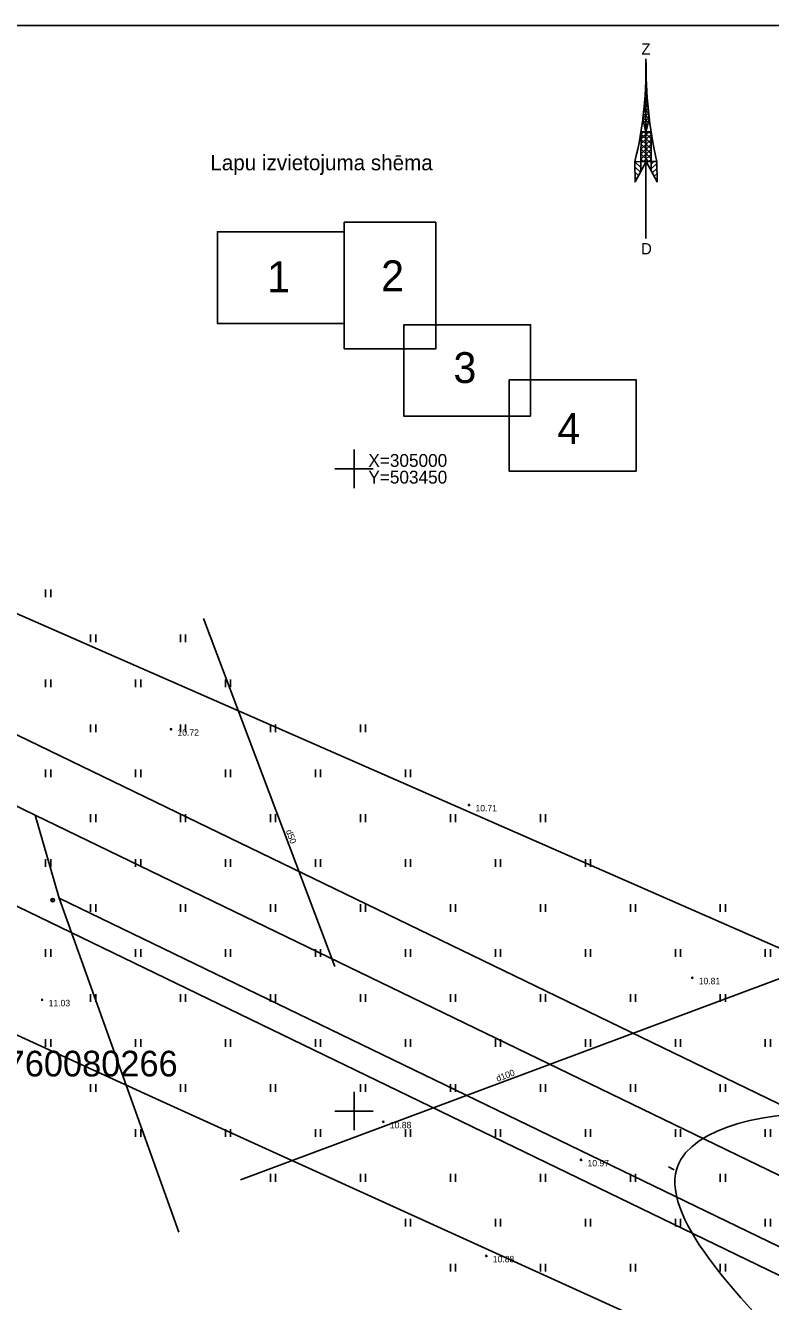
# Model space of a CAD drawing. Extents: x 503353 to 504004, y 304662 to 305049.
# Drawn here: x 503424.4 to 503482.4, y 304935.2 to 305034.5 of the extents above; entities that cross this region are included whole.
import ezdxf

# ---------------------------------------------------------------- set-up
doc = ezdxf.new("R2010")
doc.units = 0
for name, color, linetype in [('20', 7, 'Continuous'), ('24', 7, 'Continuous'), ('25', 7, 'Continuous'), ('59', 7, 'Continuous'), ('APGR_ELEM_####_####_#', 7, 'Continuous'), ('BUVE_ELEM_####_####_#', 7, 'Continuous'), ('DREN_VADP_####_####_#', 7, 'Continuous'), ('DREN_VADP_####_TKST_#', 7, 'Continuous'), ('DREN_VADP_KLKT_####_#', 7, 'Continuous'), ('DREN_VADP_KLKT_TKST_#', 7, 'Continuous'), ('GEOD_ELEM_####_####_#', 7, 'Continuous'), ('GEOD_KORD_####_TKST_#', 7, 'Continuous'), ('RAMI_PLAN_####_TKST_#', 7, 'Continuous'), ('RAMI_UZMR_####_####_#', 7, 'Continuous'), ('RELJ_AATZ_####_TKST_#', 7, 'Continuous'), ('RELJ_ELEM_####_####_#', 7, 'Continuous'), ('RELJ_HORZ_PAMT_####_#', 7, 'Continuous'), ('TERT_ELEM_####_####_#', 7, 'Continuous')]:
    doc.layers.add(name, color=color, linetype=linetype)

msp = doc.modelspace()

# ---------------------------------------------------------------- linework, layer by layer
at = {"layer": '20'}
msp.add_line((503425.185, 304973.036), (503427.051, 304966.576), dxfattribs=at)
at = {"layer": '24'}
for q in [(503436.371, 304940.581), (503597.271, 304884.111)]:
    msp.add_line((503427.051, 304966.576), q, dxfattribs=at)
at = {"layer": '25'}
for p in [(503405.924, 304982.367), (503595.592, 304890.48)]:
    msp.add_line(p, (503425.185, 304973.036), dxfattribs=at)
at = {"layer": 'APGR_ELEM_####_####_#'}
for p, q in [((503412.342, 304984.814), (503586.697, 304900.345)), ((503415.949, 304969.732), (503588.684, 304886.049))]:
    msp.add_line(p, q, dxfattribs=at)
at = {"layer": 'BUVE_ELEM_####_####_#'}
for radius in [0.141, 0.0126]:
    msp.add_circle((503426.558, 304966.417), radius, dxfattribs=at)
at = {"layer": 'DREN_VADP_####_####_#'}
msp.add_line((503438.283, 304988.335), (503448.499, 304961.265), dxfattribs=at)
at = {"layer": 'DREN_VADP_KLKT_####_#'}
msp.add_lwpolyline([(503441.156, 304944.635), (503491.393, 304963.409)], dxfattribs=at)
at = {"layer": 'GEOD_ELEM_####_####_#'}
for p, q in [((503450, 305001.5), (503450, 305000)), ((503448.5, 305000), (503450, 305000)), ((503450, 305000), (503450, 304998.5)), ((503450, 305000), (503451.5, 305000)), ((503450, 304951.5), (503450, 304950)), ((503448.5, 304950), (503450, 304950)), ((503450, 304950), (503450, 304948.5)), ((503450, 304950), (503451.5, 304950))]:
    msp.add_line(p, q, dxfattribs=at)
at = {"layer": 'RAMI_PLAN_####_TKST_#'}
for p, q in [((503472.715, 305031.907), (503472.715, 305017.937)), ((503472.673, 305029.405), (503472.775, 305029.504)), ((503472.675, 305029.469), (503472.783, 305029.366)), ((503472.693, 305029.814), (503472.756, 305029.873)), ((503472.695, 305029.836), (503472.759, 305029.776)), ((503472.718, 305030.206), (503472.741, 305030.184)), ((503472.579, 305028.152), (503472.853, 305028.414)), ((503472.599, 305028.378), (503472.879, 305028.11)), ((503472.614, 305028.577), (503472.822, 305028.773)), ((503472.627, 305028.738), (503472.845, 305028.532)), ((503472.647, 305028.997), (503472.793, 305029.13)), ((503472.655, 305029.096), (503472.808, 305028.954)), ((503472.481, 305027.281), (503472.916, 305027.696)), ((503472.484, 305027.323), (503472.899, 305026.926)), ((503472.523, 305027.671), (503472.966, 305027.248)), ((503472.529, 305027.719), (503472.884, 305028.055)), ((503472.542, 305026.949), (503472.957, 305027.35)), ((503472.563, 305028.022), (503472.917, 305027.685)), ((503472.562, 305026.861), (503472.818, 305026.614)), ((503472.614, 305026.632), (503472.89, 305026.896)), ((503472.676, 305026.359), (503472.736, 305026.303)), ((503472.687, 305026.314), (503472.758, 305026.384)), ((503472.322, 305024.893), (503473.115, 305025.648)), ((503472.325, 305025.286), (503473.113, 305026.034)), ((503472.325, 305025.286), (503473.116, 305024.532)), ((503472.328, 305025.676), (503472.928, 305026.245)), ((503472.328, 305025.666), (503473.116, 305024.921)), ((503472.332, 305026.066), (503472.518, 305026.245)), ((503472.332, 305026.053), (503473.115, 305025.309)), ((503472.539, 305026.245), (503473.115, 305025.698)), ((503472.948, 305026.245), (503473.113, 305026.087)), ((503472.314, 305024.108), (503473.116, 305024.871)), ((503472.317, 305024.499), (503473.115, 305025.26)), ((503472.317, 305024.515), (503472.943, 305023.921)), ((503472.322, 305024.899), (503473.118, 305024.142)), ((503472.524, 305023.921), (503473.116, 305024.482)), ((503471.845, 305023.887), (503471.867, 305022.338)), ((503471.848, 305023.887), (503472.311, 305023.451)), ((503471.85, 305023.496), (503472.279, 305023.095)), ((503471.867, 305022.338), (503472.728, 305023.912)), ((503472.226, 305023.916), (503472.312, 305023.834)), ((503472.314, 305024.128), (503472.534, 305023.921)), ((503472.728, 305023.912), (503473.585, 305022.338)), ((503472.93, 305023.921), (503473.118, 305024.098)), ((503473.116, 305023.34), (503473.566, 305023.765)), ((503473.118, 305023.727), (503473.315, 305023.916)), ((503473.205, 305023.032), (503473.57, 305023.384)), ((503473.585, 305022.338), (503473.563, 305023.912)), ((503471.855, 305023.103), (503472.139, 305022.838)), ((503471.862, 305022.708), (503471.999, 305022.579)), ((503471.867, 305022.345), (503471.876, 305022.354)), ((503473.344, 305022.779), (503473.575, 305022.998)), ((503473.483, 305022.524), (503473.582, 305022.614)), ((503473.585, 305022.341), (503473.585, 305022.341))]:
    msp.add_line(p, q, dxfattribs=at)
for points in [[(503550.18, 304891.905), (503352.996, 304891.905), (503352.996, 305034.51), (503550.18, 305034.51)], [(503472.714, 305026.206), (503472.474, 305027.237), (503472.584, 305028.193), (503472.654, 305029.067), (503472.716, 305030.206), (503472.737, 305030.206), (503472.793, 305029.13), (503472.909, 305027.761), (503472.971, 305027.213)], [(503472.334, 305026.245), (503473.113, 305026.245), (503473.118, 305023.919), (503472.312, 305023.923)], [(503472.312, 305023.923), (503472.31, 305023.149), (503471.867, 305022.338), (503471.845, 305023.887)], [(503473.118, 305023.919), (503473.116, 305023.189), (503473.585, 305022.338), (503473.563, 305023.912)], [(503449.235, 305011.323), (503439.376, 305011.323), (503439.376, 305018.453), (503449.235, 305018.453)], [(503456.365, 305019.199), (503456.365, 305009.34), (503449.235, 305009.34), (503449.235, 305019.199)], [(503463.74, 305004.087), (503453.881, 305004.087), (503453.881, 305011.217), (503463.74, 305011.217)], [(503471.942, 304999.803), (503462.083, 304999.803), (503462.083, 305006.933), (503471.942, 305006.933)]]:
    msp.add_lwpolyline(points, close=True, dxfattribs=at)
for centre, major_axis, start_param, end_param in [((503440.382, 305031.023), (32.345, 0), 6.048896, 6.311872), ((503511.053, 305031.539), (-38.341, 0), 6.273156, 6.494161)]:
    msp.add_ellipse(centre, major_axis=major_axis, ratio=0.950423, start_param=start_param, end_param=end_param, dxfattribs=at)
at = {"layer": 'RAMI_UZMR_####_####_#'}
for points in [[(503407.219, 305023.925), (503368.776, 305020.183), (503379.431, 304977.462), (503383.452, 304957.421), (503396.867, 304960.598), (503416.959, 304959.032), (503433.698, 304951.36), (503608.791, 304871.751), (503642.724, 304858.177), (503694.651, 304834.724), (503842.283, 304765.867)], [(503825.923, 304784.828), (503697.433, 304847.709), (503608.51, 304889.842), (503606.524, 304897.202), (503679.244, 304999.942), (503684.897, 305009.76), (503666.777, 305017.939), (503656.134, 304996.39), (503644.103, 304987.6), (503600.987, 304924.263), (503587.985, 304916.668), (503422.237, 304989.372), (503408.615, 305023.495), (503368.776, 305020.183)]]:
    msp.add_lwpolyline(points, dxfattribs=at)
at = {"layer": 'RELJ_ELEM_####_####_#'}
for centre in [(503435.76, 304979.722), (503458.948, 304973.827), (503476.316, 304960.372), (503425.735, 304958.657), (503452.285, 304949.16), (503467.669, 304946.195), (503460.297, 304938.724)]:
    msp.add_circle(centre, 0.05, dxfattribs=at)
at = {"layer": 'RELJ_HORZ_PAMT_####_#'}
msp.add_line((503474.465, 304945.655), (503474.914, 304945.435), dxfattribs=at)
msp.add_spline([(503515.837, 304912.452), (503529.269, 304910.776), (503540.552, 304906.064), (503546.637, 304910.871), (503542.749, 304919.71), (503537.502, 304925.719), (503521.557, 304942.195), (503504.791, 304943.097), (503497.964, 304945.184), (503488.514, 304949.453), (503475.429, 304946.228), (503484.342, 304930.921), (503496.131, 304918.619)], degree=3, dxfattribs=at)
at = {"layer": 'TERT_ELEM_####_####_#'}
for p, q in [((503426, 304990), (503426, 304990.6)), ((503426.4, 304990), (503426.4, 304990.6)), ((503429.5, 304986.5), (503429.5, 304987.1)), ((503429.9, 304986.5), (503429.9, 304987.1)), ((503436.5, 304986.5), (503436.5, 304987.1)), ((503436.9, 304986.5), (503436.9, 304987.1)), ((503426, 304983), (503426, 304983.6)), ((503426.4, 304983), (503426.4, 304983.6)), ((503433, 304983), (503433, 304983.6)), ((503433.4, 304983), (503433.4, 304983.6)), ((503440, 304983), (503440, 304983.6)), ((503440.4, 304983), (503440.4, 304983.6)), ((503429.5, 304979.5), (503429.5, 304980.1)), ((503429.9, 304979.5), (503429.9, 304980.1)), ((503436.5, 304979.5), (503436.5, 304980.1)), ((503436.9, 304979.5), (503436.9, 304980.1)), ((503443.5, 304979.5), (503443.5, 304980.1)), ((503443.9, 304979.5), (503443.9, 304980.1)), ((503450.5, 304979.5), (503450.5, 304980.1)), ((503450.9, 304979.5), (503450.9, 304980.1)), ((503426, 304976), (503426, 304976.6)), ((503426.4, 304976), (503426.4, 304976.6)), ((503433, 304976), (503433, 304976.6)), ((503433.4, 304976), (503433.4, 304976.6)), ((503440, 304976), (503440, 304976.6)), ((503440.4, 304976), (503440.4, 304976.6)), ((503447, 304976), (503447, 304976.6)), ((503447.4, 304976), (503447.4, 304976.6)), ((503454, 304976), (503454, 304976.6)), ((503454.4, 304976), (503454.4, 304976.6)), ((503429.5, 304972.5), (503429.5, 304973.1)), ((503429.9, 304972.5), (503429.9, 304973.1)), ((503436.5, 304972.5), (503436.5, 304973.1)), ((503436.9, 304972.5), (503436.9, 304973.1)), ((503443.5, 304972.5), (503443.5, 304973.1)), ((503443.9, 304972.5), (503443.9, 304973.1)), ((503450.5, 304972.5), (503450.5, 304973.1)), ((503450.9, 304972.5), (503450.9, 304973.1)), ((503457.5, 304972.5), (503457.5, 304973.1)), ((503457.9, 304972.5), (503457.9, 304973.1)), ((503464.5, 304972.5), (503464.5, 304973.1)), ((503464.9, 304972.5), (503464.9, 304973.1)), ((503426, 304969), (503426, 304969.6)), ((503426.4, 304969), (503426.4, 304969.6)), ((503433, 304969), (503433, 304969.6)), ((503433.4, 304969), (503433.4, 304969.6)), ((503440, 304969), (503440, 304969.6)), ((503440.4, 304969), (503440.4, 304969.6)), ((503447, 304969), (503447, 304969.6)), ((503447.4, 304969), (503447.4, 304969.6)), ((503454, 304969), (503454, 304969.6)), ((503454.4, 304969), (503454.4, 304969.6)), ((503461, 304969), (503461, 304969.6)), ((503461.4, 304969), (503461.4, 304969.6)), ((503468, 304969), (503468, 304969.6)), ((503468.4, 304969), (503468.4, 304969.6)), ((503429.5, 304965.5), (503429.5, 304966.1)), ((503429.9, 304965.5), (503429.9, 304966.1)), ((503436.5, 304965.5), (503436.5, 304966.1)), ((503436.9, 304965.5), (503436.9, 304966.1)), ((503443.5, 304965.5), (503443.5, 304966.1)), ((503443.9, 304965.5), (503443.9, 304966.1)), ((503450.5, 304965.5), (503450.5, 304966.1)), ((503450.9, 304965.5), (503450.9, 304966.1)), ((503457.5, 304965.5), (503457.5, 304966.1)), ((503457.9, 304965.5), (503457.9, 304966.1)), ((503464.5, 304965.5), (503464.5, 304966.1)), ((503464.9, 304965.5), (503464.9, 304966.1)), ((503471.5, 304965.5), (503471.5, 304966.1)), ((503471.9, 304965.5), (503471.9, 304966.1)), ((503478.5, 304965.5), (503478.5, 304966.1)), ((503478.9, 304965.5), (503478.9, 304966.1)), ((503426, 304962), (503426, 304962.6)), ((503426.4, 304962), (503426.4, 304962.6)), ((503433, 304962), (503433, 304962.6)), ((503433.4, 304962), (503433.4, 304962.6)), ((503440, 304962), (503440, 304962.6)), ((503440.4, 304962), (503440.4, 304962.6)), ((503447, 304962), (503447, 304962.6)), ((503447.4, 304962), (503447.4, 304962.6)), ((503454, 304962), (503454, 304962.6)), ((503454.4, 304962), (503454.4, 304962.6)), ((503461, 304962), (503461, 304962.6)), ((503461.4, 304962), (503461.4, 304962.6)), ((503468, 304962), (503468, 304962.6)), ((503468.4, 304962), (503468.4, 304962.6)), ((503475, 304962), (503475, 304962.6)), ((503475.4, 304962), (503475.4, 304962.6)), ((503482, 304962), (503482, 304962.6)), ((503482.4, 304962), (503482.4, 304962.6)), ((503429.5, 304958.5), (503429.5, 304959.1)), ((503429.9, 304958.5), (503429.9, 304959.1)), ((503436.5, 304958.5), (503436.5, 304959.1)), ((503436.9, 304958.5), (503436.9, 304959.1)), ((503443.5, 304958.5), (503443.5, 304959.1)), ((503443.9, 304958.5), (503443.9, 304959.1)), ((503450.5, 304958.5), (503450.5, 304959.1)), ((503450.9, 304958.5), (503450.9, 304959.1)), ((503457.5, 304958.5), (503457.5, 304959.1)), ((503457.9, 304958.5), (503457.9, 304959.1)), ((503464.5, 304958.5), (503464.5, 304959.1)), ((503464.9, 304958.5), (503464.9, 304959.1)), ((503471.5, 304958.5), (503471.5, 304959.1)), ((503471.9, 304958.5), (503471.9, 304959.1)), ((503478.5, 304958.5), (503478.5, 304959.1)), ((503478.9, 304958.5), (503478.9, 304959.1)), ((503426, 304955), (503426, 304955.6)), ((503426.4, 304955), (503426.4, 304955.6)), ((503433, 304955), (503433, 304955.6)), ((503433.4, 304955), (503433.4, 304955.6)), ((503440, 304955), (503440, 304955.6)), ((503440.4, 304955), (503440.4, 304955.6)), ((503447, 304955), (503447, 304955.6)), ((503447.4, 304955), (503447.4, 304955.6)), ((503454, 304955), (503454, 304955.6)), ((503454.4, 304955), (503454.4, 304955.6)), ((503461, 304955), (503461, 304955.6)), ((503461.4, 304955), (503461.4, 304955.6)), ((503468, 304955), (503468, 304955.6)), ((503468.4, 304955), (503468.4, 304955.6)), ((503475, 304955), (503475, 304955.6)), ((503475.4, 304955), (503475.4, 304955.6)), ((503482, 304955), (503482, 304955.6)), ((503482.4, 304955), (503482.4, 304955.6)), ((503429.5, 304951.5), (503429.5, 304952.1)), ((503429.9, 304951.5), (503429.9, 304952.1)), ((503436.5, 304951.5), (503436.5, 304952.1)), ((503436.9, 304951.5), (503436.9, 304952.1)), ((503443.5, 304951.5), (503443.5, 304952.1)), ((503443.9, 304951.5), (503443.9, 304952.1)), ((503450.5, 304951.5), (503450.5, 304952.1)), ((503450.9, 304951.5), (503450.9, 304952.1)), ((503457.5, 304951.5), (503457.5, 304952.1)), ((503457.9, 304951.5), (503457.9, 304952.1)), ((503464.5, 304951.5), (503464.5, 304952.1)), ((503464.9, 304951.5), (503464.9, 304952.1)), ((503471.5, 304951.5), (503471.5, 304952.1)), ((503471.9, 304951.5), (503471.9, 304952.1)), ((503478.5, 304951.5), (503478.5, 304952.1)), ((503478.9, 304951.5), (503478.9, 304952.1)), ((503433, 304948), (503433, 304948.6)), ((503433.4, 304948), (503433.4, 304948.6)), ((503440, 304948), (503440, 304948.6)), ((503440.4, 304948), (503440.4, 304948.6)), ((503447, 304948), (503447, 304948.6)), ((503447.4, 304948), (503447.4, 304948.6)), ((503454, 304948), (503454, 304948.6)), ((503454.4, 304948), (503454.4, 304948.6)), ((503461, 304948), (503461, 304948.6)), ((503461.4, 304948), (503461.4, 304948.6)), ((503468, 304948), (503468, 304948.6)), ((503468.4, 304948), (503468.4, 304948.6)), ((503475, 304948), (503475, 304948.6)), ((503475.4, 304948), (503475.4, 304948.6)), ((503482, 304948), (503482, 304948.6)), ((503482.4, 304948), (503482.4, 304948.6)), ((503443.5, 304944.5), (503443.5, 304945.1)), ((503443.9, 304944.5), (503443.9, 304945.1)), ((503450.5, 304944.5), (503450.5, 304945.1)), ((503450.9, 304944.5), (503450.9, 304945.1)), ((503457.5, 304944.5), (503457.5, 304945.1)), ((503457.9, 304944.5), (503457.9, 304945.1)), ((503464.5, 304944.5), (503464.5, 304945.1)), ((503464.9, 304944.5), (503464.9, 304945.1)), ((503471.5, 304944.5), (503471.5, 304945.1)), ((503471.9, 304944.5), (503471.9, 304945.1)), ((503478.5, 304944.5), (503478.5, 304945.1)), ((503478.9, 304944.5), (503478.9, 304945.1)), ((503454, 304941), (503454, 304941.6)), ((503454.4, 304941), (503454.4, 304941.6)), ((503461, 304941), (503461, 304941.6)), ((503461.4, 304941), (503461.4, 304941.6)), ((503468, 304941), (503468, 304941.6)), ((503468.4, 304941), (503468.4, 304941.6)), ((503475, 304941), (503475, 304941.6)), ((503475.4, 304941), (503475.4, 304941.6)), ((503482, 304941), (503482, 304941.6)), ((503482.4, 304941), (503482.4, 304941.6)), ((503457.5, 304937.5), (503457.5, 304938.1)), ((503457.9, 304937.5), (503457.9, 304938.1)), ((503464.5, 304937.5), (503464.5, 304938.1)), ((503464.9, 304937.5), (503464.9, 304938.1)), ((503471.5, 304937.5), (503471.5, 304938.1)), ((503471.9, 304937.5), (503471.9, 304938.1)), ((503478.5, 304937.5), (503478.5, 304938.1)), ((503478.9, 304937.5), (503478.9, 304938.1))]:
    msp.add_line(p, q, dxfattribs=at)

# ---------------------------------------------------------------- texts
at = {"layer": '59'}
msp.add_text('80760080266', height=2, dxfattribs=at).set_placement((503419.918, 304952.694))
at = {"layer": 'DREN_VADP_####_TKST_#'}
msp.add_text('d50', height=0.5, rotation=290.67609, dxfattribs=at).set_placement((503444.683, 304971.803))
at = {"layer": 'DREN_VADP_KLKT_TKST_#'}
msp.add_text('d100', height=0.5, rotation=20.4917, dxfattribs=at).set_placement((503461.164, 304952.273))
at = {"layer": 'GEOD_KORD_####_TKST_#'}
for s, p in [('   X=305000', (503450, 305000.15)), ('   Y=503450', (503450, 304998.85))]:
    msp.add_text(s, height=1, dxfattribs=at).set_placement(p)
at = {"layer": 'RAMI_PLAN_####_TKST_#'}
for s, p in [('Z', (503472.36, 305032.247)), ('D', (503472.326, 305016.694))]:
    msp.add_text(s, height=0.878, rotation=360, dxfattribs=at).set_placement(p)
for s, height, p in [('Lapu izvietojuma shēma', 1.2, (503438.82, 305023.238)), ('1', 2.4, (503443.241, 305013.748)), ('2', 2.4, (503452.108, 305013.826)), ('3', 2.4, (503457.733, 305006.679)), ('4', 2.4, (503465.824, 305001.935))]:
    msp.add_text(s, height=height, dxfattribs=at).set_placement(p)
at = {"layer": 'RELJ_AATZ_####_TKST_#'}
for s, p in [('10.72', (503436.26, 304979.222)), ('10.71', (503459.448, 304973.327)), ('10.81', (503476.816, 304959.872)), ('11.03', (503426.235, 304958.157)), ('10.88', (503452.785, 304948.66)), ('10.97', (503468.169, 304945.695)), ('10.88', (503460.797, 304938.224))]:
    msp.add_text(s, height=0.5, dxfattribs=at).set_placement(p)

doc.saveas('drawing.dxf')
